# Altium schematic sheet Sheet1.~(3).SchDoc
size A; SheetNumber: 1; SheetTotal: 1
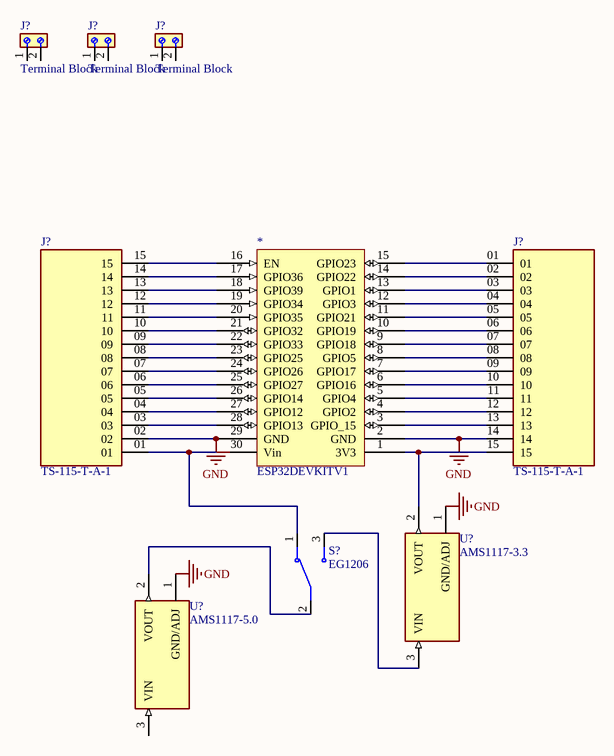
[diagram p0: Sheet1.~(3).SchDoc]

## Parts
(Parts that share a designator on the sheet are numbered #1, #2 ... from top to bottom, then left to right.)
*  ESP32DEVKITV1  [ESP32DEVKITV1]
J?#1  Terminal Block  [691213510002]
J?#2  Terminal Block  [691213510002]
J?#3  Terminal Block  [691213510002]
J?#4  TS-115-T-A-1  [SAMTEC_TS-115-T-A-1]
J?#5  TS-115-T-A-1  [SAMTEC_TS-115-T-A-1]
S?  EG1206  [SW_EG1206]
U?#1  AMS1117-3.3  [SOT229P700X180-4N]
U?#2  AMS1117-5.0  [SOT229P700X180-4N]

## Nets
GND: *.2(GND) *.29(GND) J?#4.02 J?#5.14 U?#1.1(GND/ADJ) U?#2.1(GND/ADJ)
Net*_1: *.1(3V3) J?#5.15 U?#1.2(VOUT)
Net*_3: *.3(GPIO_15) J?#5.13
Net*_4: *.4(GPIO2) J?#5.12
Net*_5: *.5(GPIO4) J?#5.11
Net*_6: *.6(GPIO16) J?#5.10
Net*_7: *.7(GPIO17) J?#5.09
Net*_8: *.8(GPIO5) J?#5.08
Net*_9: *.9(GPIO18) J?#5.07
Net*_10: *.10(GPIO19) J?#5.06
Net*_11: *.11(GPIO21) J?#5.05
Net*_12: *.12(GPIO3) J?#5.04
Net*_13: *.13(GPIO1) J?#5.03
Net*_14: *.14(GPIO22) J?#5.02
Net*_15: *.15(GPIO23) J?#5.01
Net*_16: *.16(EN) J?#4.15
Net*_17: *.17(GPIO36) J?#4.14
Net*_18: *.18(GPIO39) J?#4.13
Net*_19: *.19(GPIO34) J?#4.12
Net*_20: *.20(GPIO35) J?#4.11
Net*_21: *.21(GPIO32) J?#4.10
Net*_22: *.22(GPIO33) J?#4.09
Net*_23: *.23(GPIO25) J?#4.08
Net*_24: *.24(GPIO26) J?#4.07
Net*_25: *.25(GPIO27) J?#4.06
Net*_26: *.26(GPIO14) J?#4.05
Net*_27: *.27(GPIO12) J?#4.04
Net*_28: *.28(GPIO13) J?#4.03
Net*_30: *.30(Vin) J?#4.01 S?.1
NetS?_2: S?.2 U?#2.2(VOUT)
NetS?_3: S?.3 U?#1.3(VIN)

Not connected (* = marked no-connect by the designer): J?#1 1 2; J?#2 1 2; J?#3 1 2; U?#2 3(VIN)

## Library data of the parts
J?#1-J?#3 = Terminal Block: 2 Position Wire to Board Terminal Block Horizontal with Board 0.200 (5.08mm) Through Hole; MF: Wurth Electronics
J?#4 J?#5 = TS-115-T-A-1: MF: {'manufacturer': u'Samtec'}
S? = EG1206: MF: {'manufacturer': u'E-Switch'}
U?#1 = AMS1117-3.3: MF: {'manufacturer': u'Advanced Monolithic Systems'}
U?#2 = AMS1117-5.0: MF: {'manufacturer': u'Advanced Monolithic Systems'}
